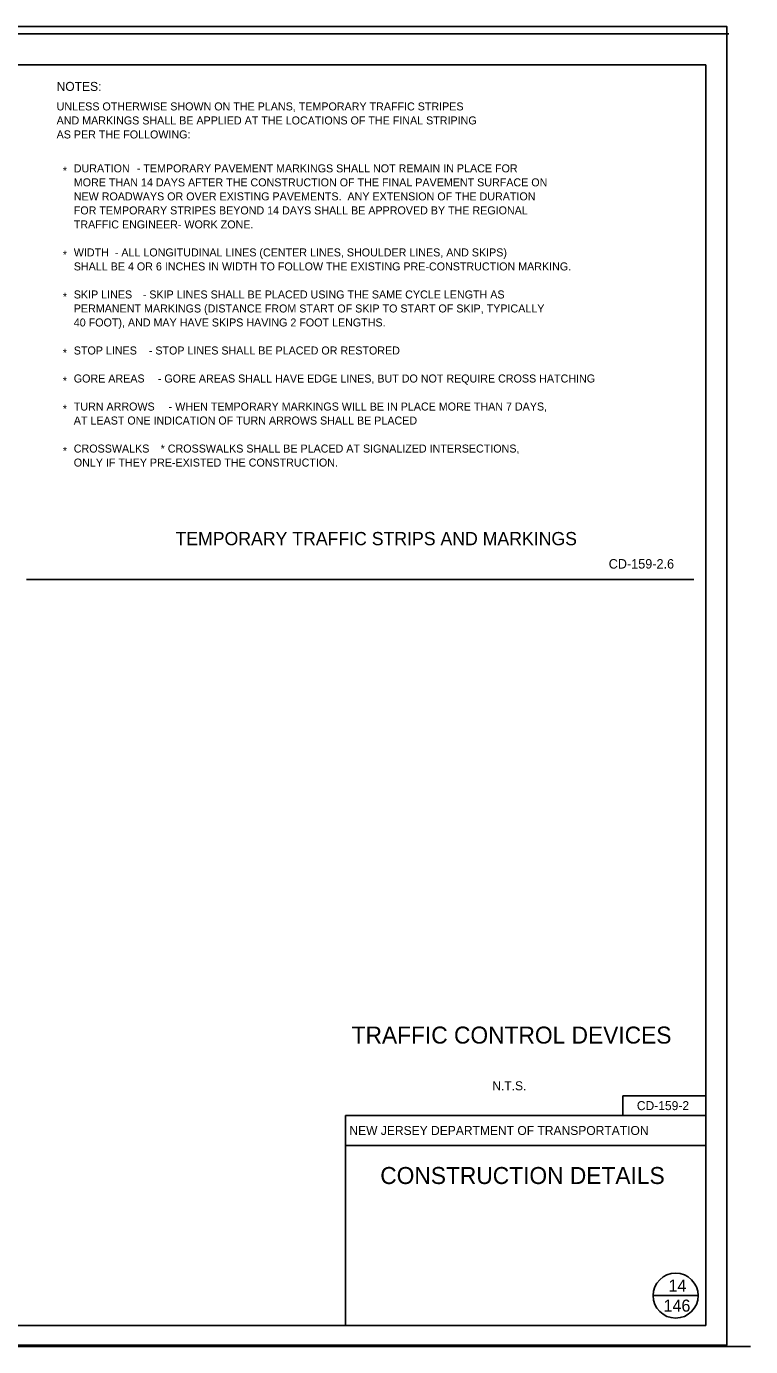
# Model space of a CAD drawing. Extents: x 499940 to 501012, y 499990 to 500649.
# Drawn here: x 500651 to 501012, y 499990 to 500649 of the extents above; entities that cross this region are included whole.
import ezdxf

# ---------------------------------------------------------------- set-up
doc = ezdxf.new("R2010")
doc.units = 0
for name, color, linetype in [('1', 7, 'Continuous'), ('10', 7, 'Continuous'), ('3', 7, 'Continuous'), ('39', 7, 'Continuous'), ('41', 7, 'Continuous'), ('5', 7, 'Continuous'), ('63', 7, 'Continuous')]:
    doc.layers.add(name, color=color, linetype=linetype)

msp = doc.modelspace()

# ---------------------------------------------------------------- linework, layer by layer
at = {"layer": '1'}
for p, q in [((500990, 500630), (500000, 500630)), ((500990, 500000), (500990, 500630)), ((500990, 500114.84), (500948.66, 500114.84)), ((500948.66, 500114.84), (500948.66, 500105)), ((500990, 500105), (500810, 500105)), ((500810, 500105), (500810, 500000)), ((500990, 500090), (500810, 500090)), ((500975, 500015), (500963.75, 500015)), ((500975, 500015), (500986.25, 500015)), ((500000, 500000), (500990, 500000)), ((499946.96, 499989.52), (501012.44, 499989.52))]:
    msp.add_line(p, q, dxfattribs=at)
msp.add_lwpolyline([(499956.44, 500645.46), (500590.04, 500645.46), (501001.61, 500645.46)], dxfattribs=at)
msp.add_circle((500975, 500015), 11.25, dxfattribs=at)
at = {"layer": '10'}
msp.add_line((500650.76, 500372.76), (500984.06, 500372.76), dxfattribs=at)
at = {"layer": '41'}
msp.add_line((500969.33, 500109.92), (500969.33, 500109.92), dxfattribs=at)
msp.add_lwpolyline([(499939.98, 499990.18), (501000.54, 499990.18), (501000.54, 500649.16), (499939.98, 500649.16)], close=True, dxfattribs=at)

# ---------------------------------------------------------------- texts
at = {"layer": '1'}
for s, height, p in [('TEMPORARY TRAFFIC STRIPS AND MARKINGS', 6.6001, (500725.14, 500389.94)), ('CD-159-2', 4.5, (500955.62, 500107.67)), ('NEW JERSEY DEPARTMENT OF TRANSPORTATION', 4.5, (500812.02, 500095.25)), ('CONSTRUCTION DETAILS', 8.5, (500827.44, 500070.75)), ('146', 6, (500968.97, 500007))]:
    msp.add_text(s, height=height, dxfattribs=at).set_placement(p)
at = {"layer": '3'}
for s, p in [('UNLESS OTHERWISE SHOWN ON THE PLANS, TEMPORARY TRAFFIC STRIPES ', (500665.77, 500607.18)), ('AND MARKINGS SHALL BE APPLIED AT THE LOCATIONS OF THE FINAL STRIPING ', (500665.77, 500600.18)), ('AS PER THE FOLLOWING:', (500665.77, 500593.18)), ('*', (500668.87, 500575.09)), ('DURATION', (500674.35, 500576.23)), (' - TEMPORARY PAVEMENT MARKINGS SHALL NOT REMAIN IN PLACE FOR', (500704.36, 500576.23)), ('MORE THAN 14 DAYS AFTER THE CONSTRUCTION OF THE FINAL PAVEMENT SURFACE ON ', (500674.35, 500569.23)), ('NEW ROADWAYS OR OVER EXISTING PAVEMENTS.  ANY EXTENSION OF THE DURATION ', (500674.35, 500562.23)), ('FOR TEMPORARY STRIPES BEYOND 14 DAYS SHALL BE APPROVED BY THE REGIONAL ', (500674.35, 500555.23)), ('TRAFFIC ENGINEER- WORK ZONE.', (500674.35, 500548.23)), ('WIDTH', (500674.35, 500534.23)), (' - ALL LONGITUDINAL LINES (CENTER LINES, SHOULDER LINES, AND SKIPS) ', (500693.36, 500534.23)), ('*', (500668.87, 500533.09)), ('SHALL BE 4 OR 6 INCHES IN WIDTH TO FOLLOW THE EXISTING PRE-CONSTRUCTION MARKING.', (500674.35, 500527.23)), ('*', (500668.87, 500512.09)), ('SKIP LINES', (500674.35, 500513.23)), (' - SKIP LINES SHALL BE PLACED USING THE SAME CYCLE LENGTH AS ', (500707.32, 500513.23)), ('PERMANENT MARKINGS (DISTANCE FROM START OF SKIP TO START OF SKIP, TYPICALLY ', (500674.35, 500506.23)), ('40 FOOT), AND MAY HAVE SKIPS HAVING 2 FOOT LENGTHS.', (500674.35, 500499.23)), ('*', (500668.87, 500484.09)), ('STOP LINES', (500674.35, 500485.23)), (' - STOP LINES SHALL BE PLACED OR RESTORED ', (500710.33, 500485.23)), ('*', (500668.87, 500470.09)), ('GORE AREAS', (500674.35, 500471.23)), (' - GORE AREAS SHALL HAVE EDGE LINES, BUT DO NOT REQUIRE CROSS HATCHING', (500714.82, 500471.23)), ('*', (500668.87, 500456.09)), ('TURN ARROWS', (500674.35, 500457.23)), (' - WHEN TEMPORARY MARKINGS WILL BE IN PLACE MORE THAN 7 DAYS, ', (500720.26, 500457.23)), ('AT LEAST ONE INDICATION OF TURN ARROWS SHALL BE PLACED', (500674.35, 500450.23)), ('CROSSWALKS', (500674.35, 500436.23)), (' * CROSSWALKS SHALL BE PLACED AT SIGNALIZED INTERSECTIONS, ', (500716.26, 500436.23)), ('*', (500668.87, 500435.09)), ('ONLY IF THEY PRE-EXISTED THE CONSTRUCTION.', (500674.35, 500429.23))]:
    msp.add_text(s, height=4, dxfattribs=at).set_placement(p)
at = {"layer": '39'}
msp.add_text('TRAFFIC CONTROL DEVICES', height=8.5, dxfattribs=at).set_placement((500813.14, 500140.92))
at = {"layer": '5'}
for s, height, p in [('NOTES:', 4.5, (500665.77, 500616.93)), ('CD-159-2.6', 4.724, (500941.56, 500378.27)), ('N.T.S.', 4.5, (500883.4, 500117.58))]:
    msp.add_text(s, height=height, dxfattribs=at).set_placement(p)
at = {"layer": '63'}
msp.add_text('14', height=6, dxfattribs=at).set_placement((500971.42, 500017))

doc.saveas('drawing.dxf')
